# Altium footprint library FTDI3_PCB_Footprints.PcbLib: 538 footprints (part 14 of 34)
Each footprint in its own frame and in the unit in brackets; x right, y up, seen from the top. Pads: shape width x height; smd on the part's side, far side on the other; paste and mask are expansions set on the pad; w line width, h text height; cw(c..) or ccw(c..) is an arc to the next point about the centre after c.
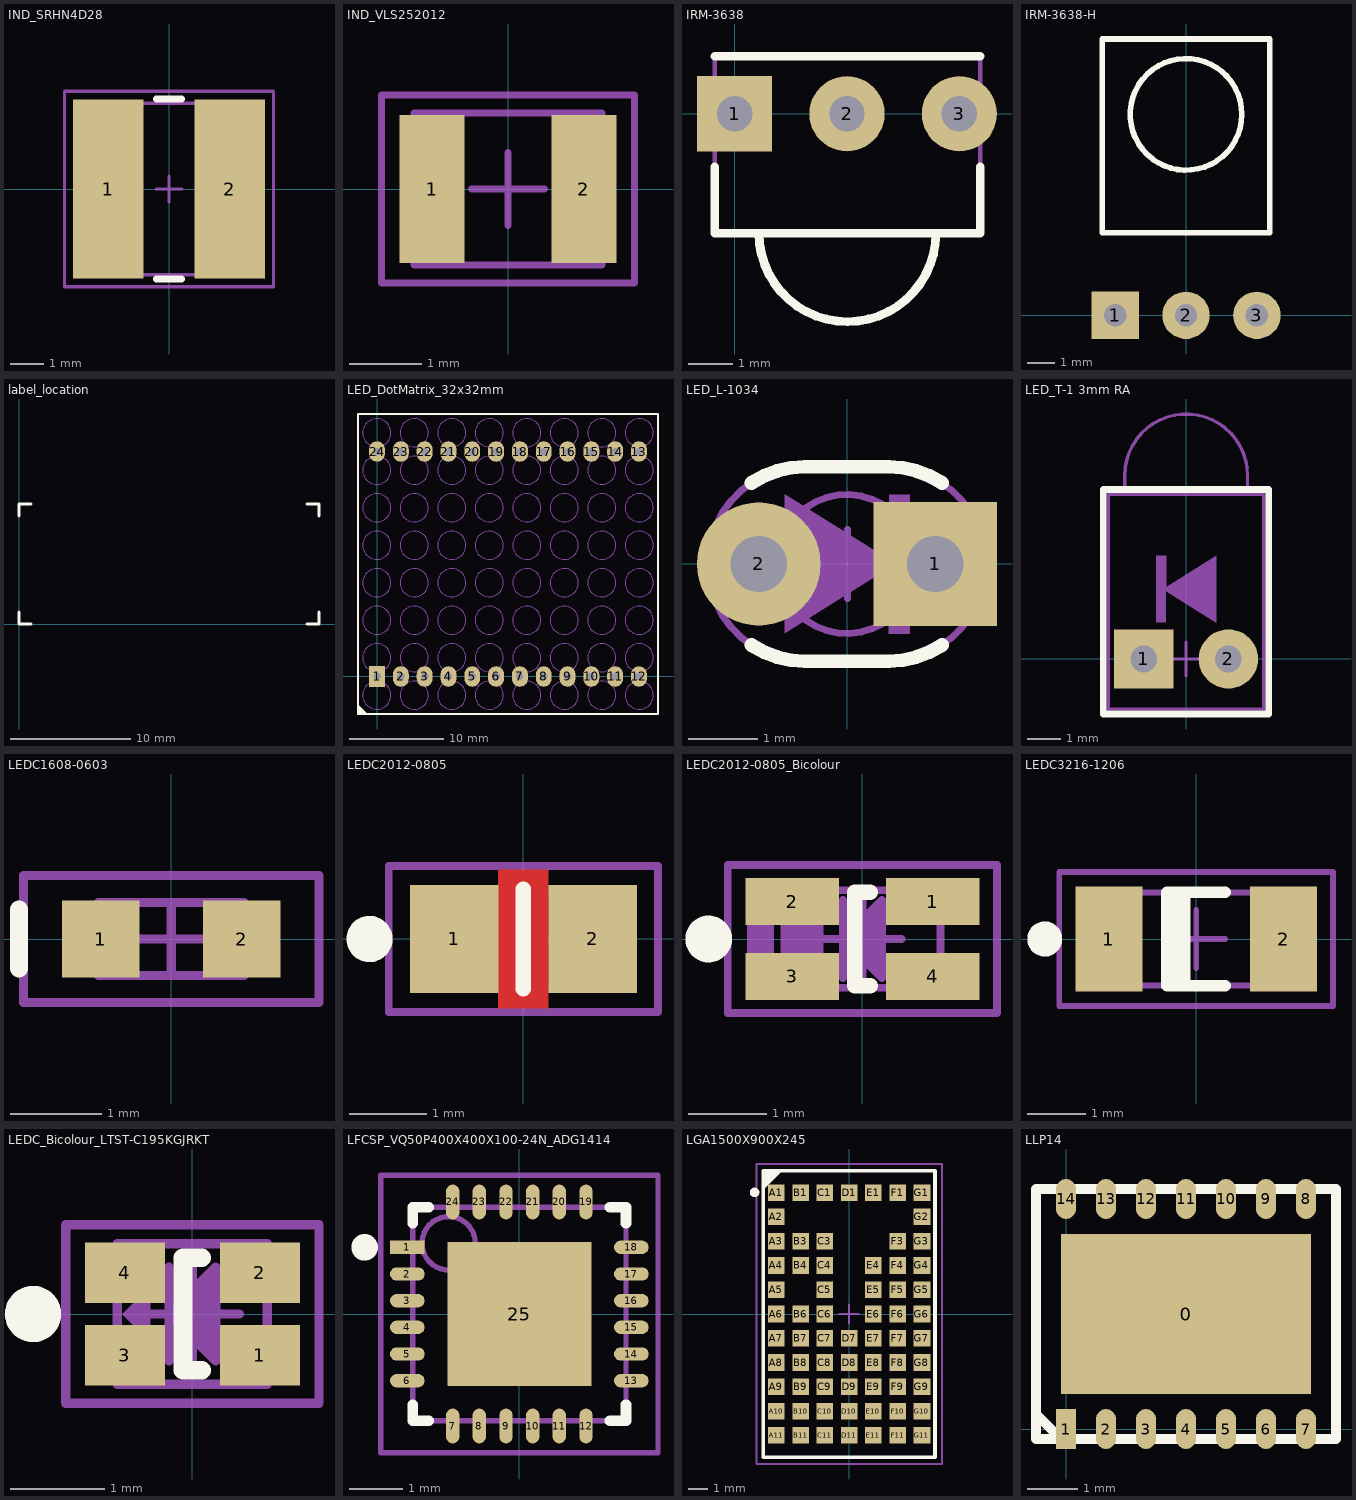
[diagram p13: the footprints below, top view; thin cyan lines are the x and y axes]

## IND_SRHN4D28 [mm] "Power Inductor SRHN4D28 series"
height 3
pads (2):
  rect 2.1x5.3 smd: 1(-1.8,0) 2(1.8,0)
Top Overlay:
  lines w0.2: -0.381,-2.667 0.381,-2.667 ; -0.381,2.667 0.381,2.667
M13_Assembly_Info:
  lines w0.1: -2.413,-2.54 2.413,-2.54 2.413,2.54 -2.413,2.54 -2.413,-2.54
M15_Country_Yard:
  lines w0.1: -0.381,0 0.381,0 ; 0,-0.381 0,0.381 ; -3.1,-2.9 3.1,-2.9 3.1,2.9 -3.1,2.9 -3.1,-2.9
3D body: height 3, standoff 0, extent -2.413,-2.54 2.413,2.54

## IND_VLS252012 [mm] "Inductor, 2-Leads, Body 2.5x2.0mm, VLS series, TDK; IPC Medium Density"
height 1.2
pads (2):
  rect 0.9x2.05 smd: 1(-1.05,0) 2(1.05,0)
M13_Assembly_Info:
  lines w0.1: -1.3,-1.05 1.3,-1.05 1.3,1.05 -1.3,1.05 -1.3,-1.05
M15_Country_Yard:
  lines w0.1: -0.5,0 0.5,0 ; 0,-0.5 0,0.5 ; -1.75,-1.3 1.75,-1.3 1.75,1.3 -1.75,1.3 -1.75,-1.3
3D body: height 1.2, standoff 0, extent -1.3,-1.05 1.3,1.05

## IRM-3638 [mm] "Infrared remote control receiver"
pads (3):
  rect 1.7x1.7 hole 0.8: 1(0,0)
  round 1.7 hole 0.8: 2(2.54,0) 3(5.08,0)
Top Overlay:
  lines w0.2: -0.45,-1.2 -0.45,-2.7 5.55,-2.7 5.55,-1.2 ; -0.45,1.3 5.55,1.3 ; 0.55,-2.7 ccw(c2.55,-2.7) 4.55,-2.7
M13_Assembly_Info:
  lines w0.1: 0.55,-2.7 ccw(c2.55,-2.7) 4.55,-2.7 ; -0.45,-2.7 5.55,-2.7 5.55,1.3 -0.45,1.3 -0.45,-2.7

## IRM-3638-H [mm] "Infrared remote control receiver"
pads (3):
  rect 1.7x1.7 hole 0.8: 1(-2.54,0)
  round 1.7 hole 0.8: 2(0,0) 3(2.54,0)
Top Overlay:
  circle w0.2: c0,7.2 r2
  lines w0.2: -3,2.95 3,2.95 3,9.9 -3,9.9 -3,2.95
M13_Assembly_Info:
  circle w0.1: c0,7.2 r2
  lines w0.1: -3,2.95 3,2.95 3,9.9 -3,9.9 -3,2.95

## label_location [mm]
Top Overlay:
  lines w0.25: 0,0 1,0 ; 0,10 1,10
  lines w0.254: 0,0 0,1 ; 0,9 0,10 ; 24,0 25,0 25,1 ; 24,10 25,10 25,9

## LED_DotMatrix_32x32mm [mm]
pads (24):
  rect 1.7x2.2 hole 0.8: 1(0,0)
  oval 1.7x2.2 hole 0.8: 2(2.54,0) 3(5.08,0) 4(7.62,0) 5(10.16,0) 6(12.7,0) 7(15.24,0) 8(17.78,0) 9(20.32,0) 10(22.86,0) 11(25.4,0) 12(27.94,0) 13(27.94,24) 14(25.4,24) 15(22.86,24) 16(20.32,24) 17(17.78,24) 18(15.24,24) 19(12.7,24) 20(10.16,24) 21(7.62,24) 22(5.08,24) 23(2.54,24) 24(0,24)
Top Overlay:
  region: -2.03,-4 -2.03,-3 -1.03,-4
  lines w0.2: -2.03,-4 -2.03,28 29.97,28 29.97,-4 -2.03,-4
M13_Assembly_Info:
  circle w0.1: c-0.03,14 r1.5
  circle w0.1: c3.97,14 r1.5
  circle w0.1: c11.97,14 r1.5
  circle w0.1: c7.97,14 r1.5
  circle w0.1: c23.97,14 r1.5
  circle w0.1: c27.97,14 r1.5
  circle w0.1: c19.97,14 r1.5
  circle w0.1: c15.97,14 r1.5
  circle w0.1: c15.97,18 r1.5
  circle w0.1: c19.97,18 r1.5
  circle w0.1: c27.97,18 r1.5
  circle w0.1: c23.97,18 r1.5
  circle w0.1: c7.97,18 r1.5
  circle w0.1: c11.97,18 r1.5
  circle w0.1: c3.97,18 r1.5
  circle w0.1: c-0.03,18 r1.5
  circle w0.1: c-0.03,26 r1.5
  circle w0.1: c3.97,26 r1.5
  circle w0.1: c11.97,26 r1.5
  circle w0.1: c7.97,26 r1.5
  circle w0.1: c23.97,26 r1.5
  circle w0.1: c27.97,26 r1.5
  circle w0.1: c19.97,26 r1.5
  circle w0.1: c15.97,26 r1.5
  circle w0.1: c15.97,22 r1.5
  circle w0.1: c19.97,22 r1.5
  circle w0.1: c27.97,22 r1.5
  circle w0.1: c23.97,22 r1.5
  circle w0.1: c7.97,22 r1.5
  circle w0.1: c11.97,22 r1.5
  circle w0.1: c3.97,22 r1.5
  circle w0.1: c-0.03,22 r1.5
  circle w0.1: c-0.03,6 r1.5
  circle w0.1: c3.97,6 r1.5
  circle w0.1: c11.97,6 r1.5
  circle w0.1: c7.97,6 r1.5
  circle w0.1: c23.97,6 r1.5
  circle w0.1: c27.97,6 r1.5
  circle w0.1: c19.97,6 r1.5
  circle w0.1: c15.97,6 r1.5
  circle w0.1: c15.97,10 r1.5
  circle w0.1: c19.97,10 r1.5
  circle w0.1: c27.97,10 r1.5
  circle w0.1: c23.97,10 r1.5
  circle w0.1: c7.97,10 r1.5
  circle w0.1: c11.97,10 r1.5
  circle w0.1: c3.97,10 r1.5
  circle w0.1: c-0.03,10 r1.5
  circle w0.1: c-0.03,2 r1.5
  circle w0.1: c3.97,2 r1.5
  circle w0.1: c11.97,2 r1.5
  circle w0.1: c7.97,2 r1.5
  circle w0.1: c23.97,2 r1.5
  circle w0.1: c27.97,2 r1.5
  circle w0.1: c19.97,2 r1.5
  circle w0.1: c15.97,2 r1.5
  circle w0.1: c15.97,-2 r1.5
  circle w0.1: c19.97,-2 r1.5
  circle w0.1: c27.97,-2 r1.5
  circle w0.1: c23.97,-2 r1.5
  circle w0.1: c7.97,-2 r1.5
  circle w0.1: c11.97,-2 r1.5
  circle w0.1: c3.97,-2 r1.5
  circle w0.1: c-0.03,-2 r1.5
  lines w0.1: -2.03,-4 -2.03,28 29.97,28 29.97,-4 -2.03,-4
3D body: height 10, standoff 0, extent -1.93,-3.9 29.87,27.9

## LED_L-1034 [mil] "2mm; Flat Top LED Lamp"
height 196.85
pads (2):
  rect 70x70 hole 32: 1(49.8,0)
  round 70 hole 32: 2(-50.2,0)
Top Overlay:
  lines w7.87: -54.36,-46.01 ccw(c-24.02,0) -24.02,-55.12 ; -54.36,46.01 cw(c-24.02,0) -24.02,55.12 ; -23.62,-55.12 23.62,-55.12 ; -23.62,55.12 23.62,55.12 ; 23.23,-55.12 ccw(c23.23,0) 53.58,-46.01 ; 23.23,55.12 cw(c23.23,0) 53.58,46.01
M13_Assembly_Info:
  circle w3.94: c-0.39,0 r39.37
  region: -35.47,39.49 -35.47,-39.21 27.48,0.12
  region: 23.74,39.29 35.35,39.29 35.35,-39.41 23.54,-39.41
  lines w3.94: -24.02,-55.12 cw(c-24.02,0) -24.02,55.12 23.23,55.12 cw(c23.23,0) 23.23,-55.12 -24.02,-55.12
M15_Country_Yard:
  lines w3.94: -19.68,0 19.69,0 ; 0,-19.68 0,19.69
3D body: height 74.8, standoff 0, extent -38.19,-39.37 40.24,39.21

## LED_T-1 3mm RA [mil] "T-1 (3 mm) Right Angle LED Indicators"
height 196.85
pads (2):
  rect 70x70 hole 31.5: 1(-50,0)
  round 70 hole 31.5: 2(50,0)
Top Overlay:
  lines w7.87: -97.44,-64.96 97.44,-64.96 97.44,200 -97.44,200 -97.44,-64.96
M13_Assembly_Info:
  region: 35.47,42.8 35.47,121.5 -27.48,82.17
  region: -23.74,42.99 -35.35,42.99 -35.35,121.69 -23.54,121.69
  lines w3.94: -72.24,194.09 -72.24,216.54 cw(c0.2,216.54) 72.64,216.54 72.64,194.09 ; -91.54,-59.06 91.54,-59.06 91.54,194.09 -91.54,194.09 -91.54,-59.06
M15_Country_Yard:
  lines w3.94: -19.68,0 19.69,0 ; 0,-19.69 0,19.68

## LEDC1608-0603 [mm] "Molded Diode, 2-Leads, Body 1.6x0.8mm, IPC Medium Density"
height 0.8
pads (2):
  rect 0.85x0.85 smd: 1(-0.775,0) 2(0.775,0)
Top Overlay:
  lines w0.2: -1.675,-0.325 -1.675,0.325
M13_Assembly_Info:
  rectangle: -0.8,-0.4 -0.4,0.4
  lines w0.1: -0.8,-0.4 0.8,-0.4 0.8,0.4 -0.8,0.4 -0.8,-0.4
M15_Country_Yard:
  lines w0.1: -0.4,0 0.4,0 ; 0,-0.4 0,0.4 ; -1.625,-0.7 1.625,-0.7 1.625,0.7 -1.625,0.7 -1.625,-0.7
3D body: height 0.8, standoff 0, extent -0.8,-0.4 0.8,0.4

## LEDC2012-0805 [mm] "Chip LED diode; Body 2 x 1.3 mm (LxW typ)"
height 0.65
pads (2):
  rect 1.15x1.4 smd: 1(-0.9,0) 2(0.9,0)
Top Layer:
  pour cut-out: -0.325,0.9 0.325,0.9 0.325,-0.9 -0.325,-0.9
Top Overlay:
  circle w0.3: c-2,0 r0.15
  lines w0.2: 0,-0.65 0,0.65
M13_Assembly_Info:
  rectangle: -1,-0.625 -0.5,0.625
  region: 0.25,-0.5 0.25,0.5 -0.25,0
  lines w0.1: -0.25,-0.5 -0.25,0.5 ; -1,-0.625 -1,0.625 1,0.625 1,-0.625 -1,-0.625 ; -0.25,0 0.25,-0.5 0.25,0.5 -0.25,0
M15_Country_Yard:
  lines w0.1: -0.35,0 0.35,0 ; 0,-0.35 0,0.35 ; -1.75,-0.95 1.75,-0.95 1.75,0.95 -1.75,0.95 -1.75,-0.95
3D body: height 1, standoff 0, extent -1,-0.625 1,0.625

## LEDC2012-0805_Bicolour [mm] "Chip LED, 4-Leads, Body 2.0x1.5mm, IPC Medium Density"
height 0.45
pads (4):
  rect 1.2x0.6 smd: 1(0.9,0.48) 2(-0.9,0.48) 3(-0.9,-0.48) 4(0.9,-0.48)
Top Overlay:
  circle w0.3: c-1.97,0 r0.15
  lines w0.2: 0.1,-0.6 -0.1,-0.6 -0.1,0.6 0.1,0.6
M13_Assembly_Info:
  rectangle: -1,-0.625 -0.5,0.625
  rectangle: -1.48,-0.18 -1.13,0.18
  region: 0.25,-0.5 0.25,0.5 -0.25,0
  lines w0.1: -0.25,-0.5 -0.25,0.5 ; -1,-0.625 -1,0.625 1,0.625 1,-0.625 -1,-0.625 ; -0.25,0 0.25,-0.5 0.25,0.5 -0.25,0
M15_Country_Yard:
  lines w0.1: -0.5,0 0.5,0 ; 0,-0.5 0,0.5 ; -1.725,-0.95 -1.725,0.95 1.725,0.95 1.725,-0.95 -1.725,-0.95
3D body: height 0.45, standoff 0, extent -1,-0.625 1,0.625

## LEDC3216-1206 [mm] "Chip LED diode; Body 3.2 x 1.6 mm (LxW typ)"
height 0.71
pads (2):
  rect 1.15x1.8 smd: 1(-1.5,0) 2(1.5,0)
Top Overlay:
  circle w0.3: c-2.6,0 r0.15
  lines w0.2: -0.35,-0.8 -0.35,0.8 ; -0.2,-0.8 -0.2,0.8 ; 0.5,-0.8 -0.5,-0.8 -0.5,0.8 0.5,0.8
M13_Assembly_Info:
  rectangle: -1.6,-0.8 -0.992,0.8
  lines w0.1: -1.6,-0.8 -1.6,0.8 1.6,0.8 1.6,-0.8 -1.6,-0.8
M15_Country_Yard:
  lines w0.1: -0.5,0 0.5,0 ; 0,-0.5 0,0.5 ; -2.35,-1.15 -2.35,1.15 2.35,1.15 2.35,-1.15 -2.35,-1.15
3D body: height 1.12, standoff -0.4, extent -1.6,-0.8 1.6,0.8

## LEDC_Bicolour_LTST-C195KGJRKT [mm] "Chip LED, 4-Leads, Body 2.0x1.5mm, IPC Medium Density"
height 0.45
pads (4):
  rect 0.85x0.65 smd: 1(0.72,-0.44) 2(0.72,0.44) 3(-0.72,-0.44) 4(-0.72,0.44)
Top Overlay:
  circle w0.3: c-1.7,0 r0.15
  lines w0.2: 0.1,-0.6 -0.1,-0.6 -0.1,0.6 0.1,0.6
M13_Assembly_Info:
  region: -0.75,0 -0.45,0.3 -0.45,-0.3
  region: 0.25,-0.5 0.25,0.5 -0.25,0
  lines w0.1: -0.25,-0.5 -0.25,0.5 ; -0.8,-0.75 -0.8,0.75 0.8,0.75 0.8,-0.75 -0.8,-0.75 ; -0.25,0 0.25,-0.5 0.25,0.5 -0.25,0
M15_Country_Yard:
  lines w0.1: -0.5,0 0.5,0 ; 0,-0.5 0,0.5 ; -1.35,-0.95 -1.35,0.95 1.35,0.95 1.35,-0.95 -1.35,-0.95
3D body: height 0.45, standoff 0, extent -0.8,-0.75 0.8,0.75

## LFCSP_VQ50P400X400X100-24N_ADG1414 [mm] "QFN, 24-Leads, Body 4.0x4.0mm (max), Pitch 0.50mm, IPC Medium Density"
height 1
pads (25):
  rect 0.65x0.25 smd: 1(-2.1,1.25)
  oval 0.65x0.25 smd: 2(-2.1,0.75) 3(-2.1,0.25) 4(-2.1,-0.25) 5(-2.1,-0.75) 6(-2.1,-1.25) 13(2.1,-1.25) 14(2.1,-0.75) 15(2.1,-0.25) 16(2.1,0.25) 17(2.1,0.75) 18(2.1,1.25)
  oval 0.25x0.65 smd: 7(-1.25,-2.1) 8(-0.75,-2.1) 9(-0.25,-2.1) 10(0.25,-2.1) 11(0.75,-2.1) 12(1.25,-2.1) 19(1.25,2.1) 20(0.75,2.1) 21(0.25,2.1) 22(-0.25,2.1) 23(-0.75,2.1) 24(-1.25,2.1)
  rect 2.7x2.7 smd: 25(0,0)
Top Overlay:
  circle w0.25: c-2.9,1.25 r0.125
  lines w0.2: -2,-1.7 -2,-2 -1.7,-2 ; -2,1.7 -2,2 -1.7,2 ; 1.7,-2 2,-2 2,-1.7 ; 1.7,2 2,2 2,1.7
M13_Assembly_Info:
  circle w0.1: c-1.325,1.325 r0.5
  lines w0.1: -2,-2 -2,2 2,2 2,-2 -2,-2
M15_Country_Yard:
  lines w0.1: -0.5,0 0.5,0 ; 0,-0.5 0,0.5 ; -2.6,-2.6 -2.6,2.6 2.6,2.6 2.6,-2.6 -2.6,-2.6
3D body: height 1, standoff 0.02, extent -2,-2 2,2

## LGA1500X900X245 [mm] "uModule, LGA, 77-Leads, Body 15.0x9.0mm,  Pitch 1.27mm, Linear Technology"
height 2.45
pads (66):
  rect 0.87x0.87 smd: A1(-3.81,6.35) A2(-3.81,5.08) A3(-3.81,3.81) A4(-3.81,2.54) A5(-3.81,1.27) A6(-3.81,0) A7(-3.81,-1.27) A8(-3.81,-2.54) A9(-3.81,-3.81) A10(-3.81,-5.08) A11(-3.81,-6.35) B1(-2.54,6.35) B3(-2.54,3.81) B4(-2.54,2.54) B6(-2.54,0) B7(-2.54,-1.27) B8(-2.54,-2.54) B9(-2.54,-3.81) B10(-2.54,-5.08) B11(-2.54,-6.35) C1(-1.27,6.35) C3(-1.27,3.81) C4(-1.27,2.54) C5(-1.27,1.27) C6(-1.27,0) C7(-1.27,-1.27) C8(-1.27,-2.54) C9(-1.27,-3.81) C10(-1.27,-5.08) C11(-1.27,-6.35) D1(0,6.35) D7(0,-1.27) D8(0,-2.54) D9(0,-3.81) D10(0,-5.08) D11(0,-6.35) E1(1.27,6.35) E4(1.27,2.54) E5(1.27,1.27) E6(1.27,0) E7(1.27,-1.27) E8(1.27,-2.54) E9(1.27,-3.81) E10(1.27,-5.08) E11(1.27,-6.35) F1(2.54,6.35) F3(2.54,3.81) F4(2.54,2.54) F5(2.54,1.27) F6(2.54,0) F7(2.54,-1.27) F8(2.54,-2.54) F9(2.54,-3.81) F10(2.54,-5.08) F11(2.54,-6.35) G1(3.81,6.35) G2(3.81,5.08) G3(3.81,3.81) G4(3.81,2.54) G5(3.81,1.27) G6(3.81,0) G7(3.81,-1.27) G8(3.81,-2.54) G9(3.81,-3.81) G10(3.81,-5.08) G11(3.81,-6.35)
Top Overlay:
  circle w0.25: c-4.95,6.365 r0.125
  region: -4.5,6.61 -3.61,7.5 -4.5,7.5
  lines w0.2: -4.5,6.61 -3.61,7.5 ; -4.5,-7.5 -4.5,7.5 4.5,7.5 4.5,-7.5 -4.5,-7.5
M13_Assembly_Info:
  lines w0.1: -4.5,-7.5 -4.5,7.5 4.5,7.5 4.5,-7.5 -4.5,-7.5
M15_Country_Yard:
  lines w0.1: -0.5,0 0.5,0 ; 0,-0.5 0,0.5 ; -4.85,-7.85 -4.85,7.85 4.85,7.85 4.85,-7.85 -4.85,-7.85
3D body: height 2.45, standoff 0, extent -4.5,-7.5 4.5,7.5

## LLP14 [mm]
pads (15):
  rect 5x3.2 smd: 0(2.4,2.3)
  rect 0.4x0.8 smd: 1(0,0)
  oval 0.4x0.8 smd: 2(0.8,0) 3(1.6,0) 4(2.4,0) 5(3.2,0) 6(4,0) 7(4.8,0) 8(4.8,4.6) 9(4,4.6) 10(3.2,4.6) 11(2.4,4.6) 12(1.6,4.6) 13(0.8,4.6) 14(0,4.6)
Top Overlay:
  lines w0.2: -0.6,0.3 -0.1,-0.2 ; -0.6,-0.2 -0.6,4.8 5.4,4.8 5.4,-0.2 -0.6,-0.2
